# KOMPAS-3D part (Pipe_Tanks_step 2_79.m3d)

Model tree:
1. X Axis
2. Y Axis
3. Z Axis  (labels: Bend 90 Dn 50; Pipe Dn 50)
     Òîëùèíà ñòåíêè 1 = 1

Referenced files in C:\Documents and Settings\kashirsky\Мои документы\Camtasia Studio\Pipelines3D\Tanks\: Tanks_step 2.a3d
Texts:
  Pipe Dn 50
  Steel ASTM A295
  Three Point Plane
  Plane at Angle
  Line and Point Plane
  Axis through Two Vertices
  Axis of Feature
  Axis of Conical Surface
  Axis through Edge
  Trim by Surface
  Trim by Sketch
  Feature with No History
  Intersection Axis of Two Planes
  Two Line Plane
  Line and Face Plane
  Bend by line
  Hole in sheet body
  Cut in sheet body
  Point in CM
  Linear Dimension from Line to Point
  Surface Finish Symbol
  Geometric Tolerance Symbol
  Leader #1
  Leader #2
  Leader #3
  Shape Deviations and Datum
  Node point number
  Mark of coordination axis
  Node point designation
  Mark/Reference designation with leader
  Mark/reference designation on line
  Mark/Reference designation without leader
  Bend 90 Dn 50
  Plane of section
